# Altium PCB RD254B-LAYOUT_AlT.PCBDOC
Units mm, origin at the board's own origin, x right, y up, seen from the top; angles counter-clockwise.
Board outline 100 x 100 mm, 2 copper layers (TOP, BOTTOM), stack 0 mm thick; 50 components, 44 nets, 384 pads, 0 vias.
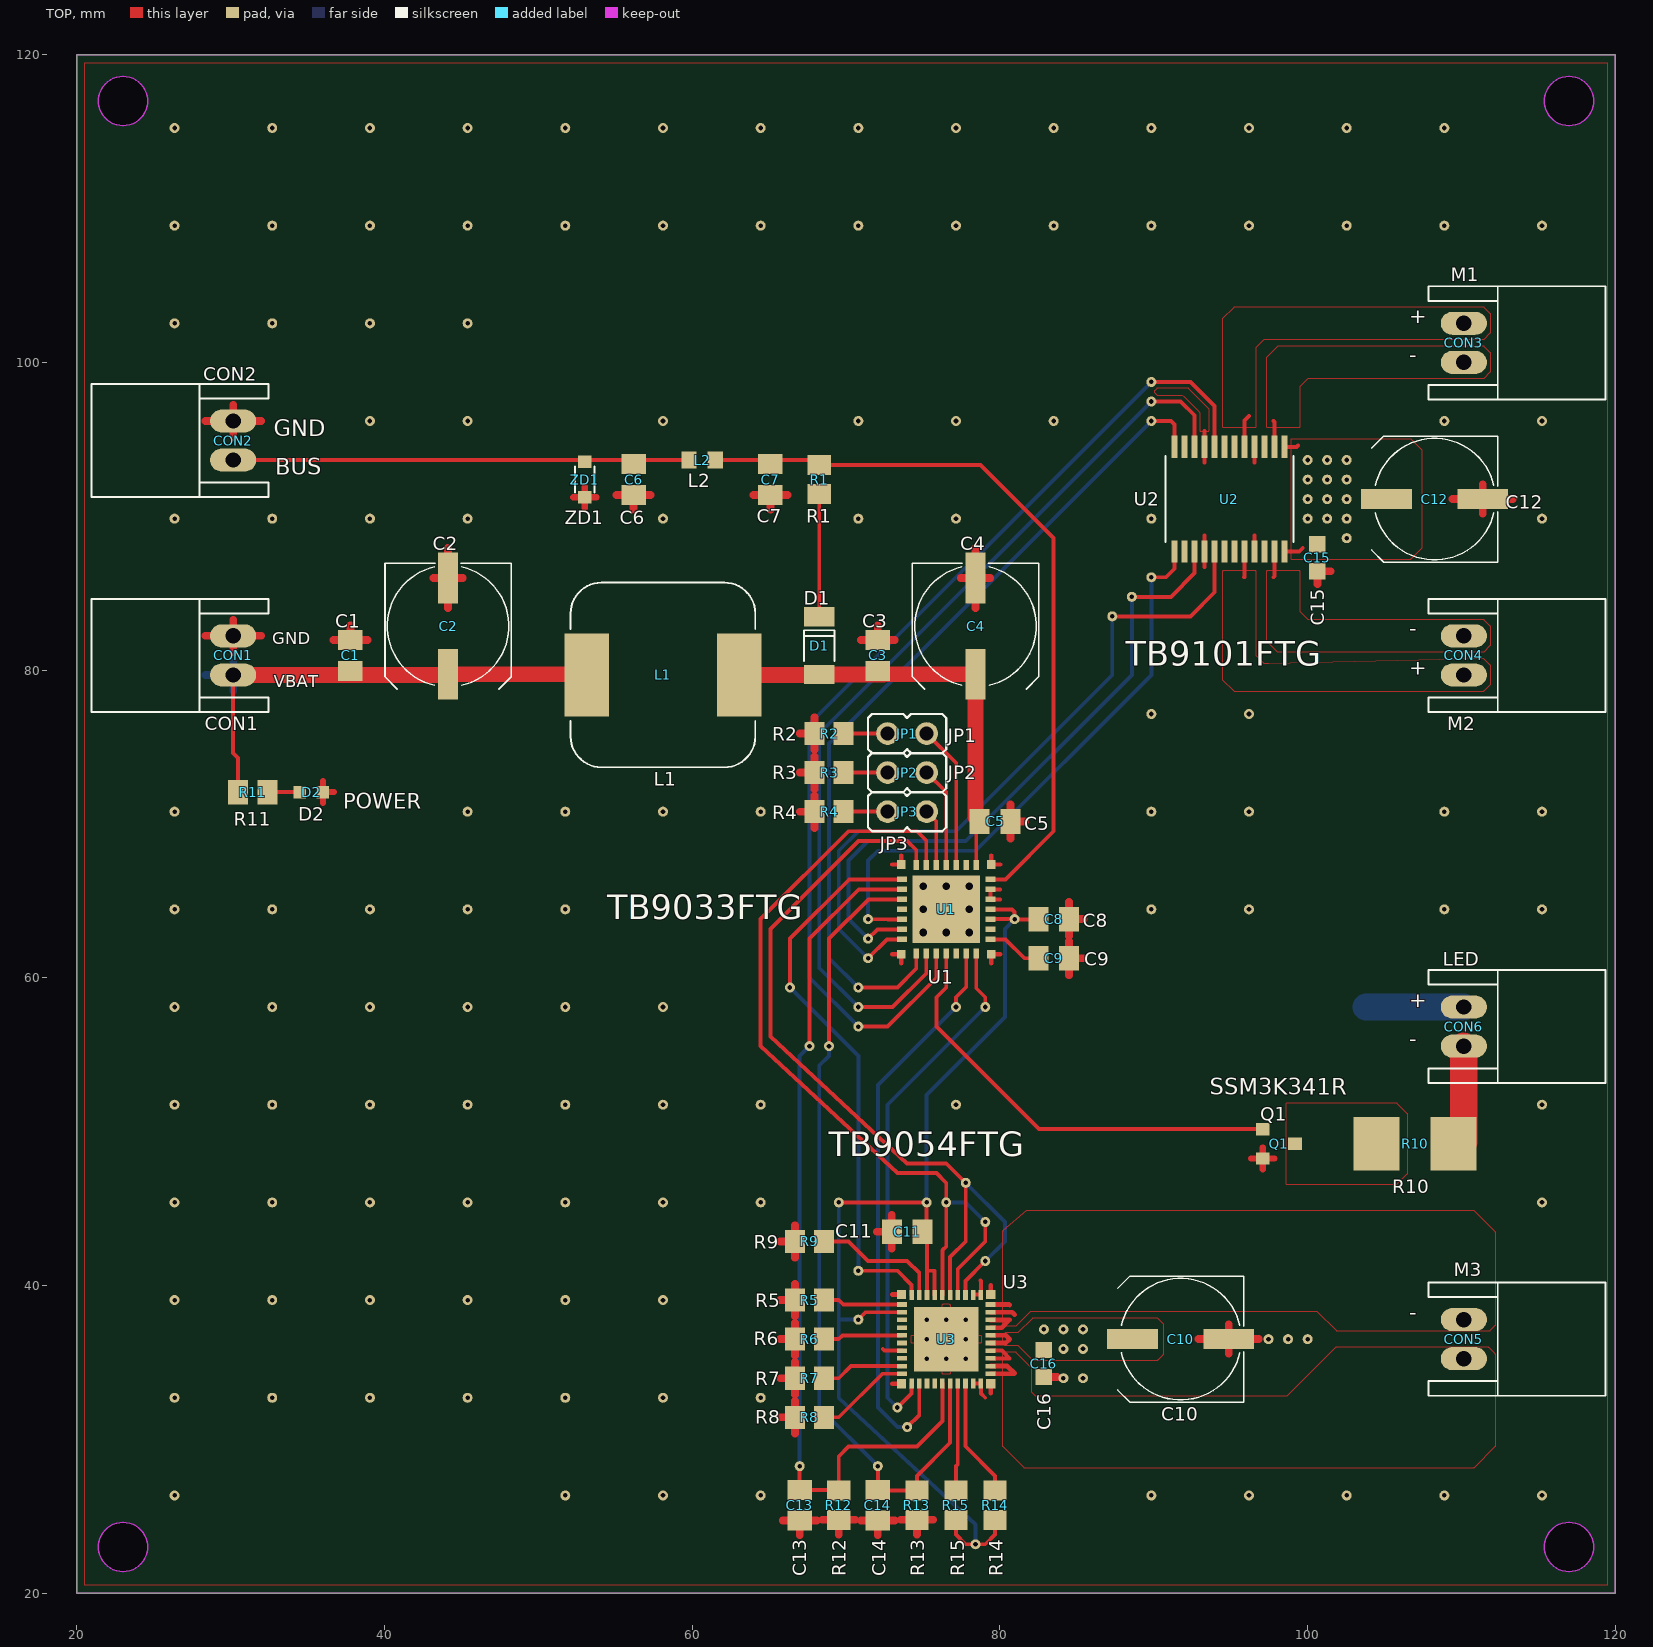
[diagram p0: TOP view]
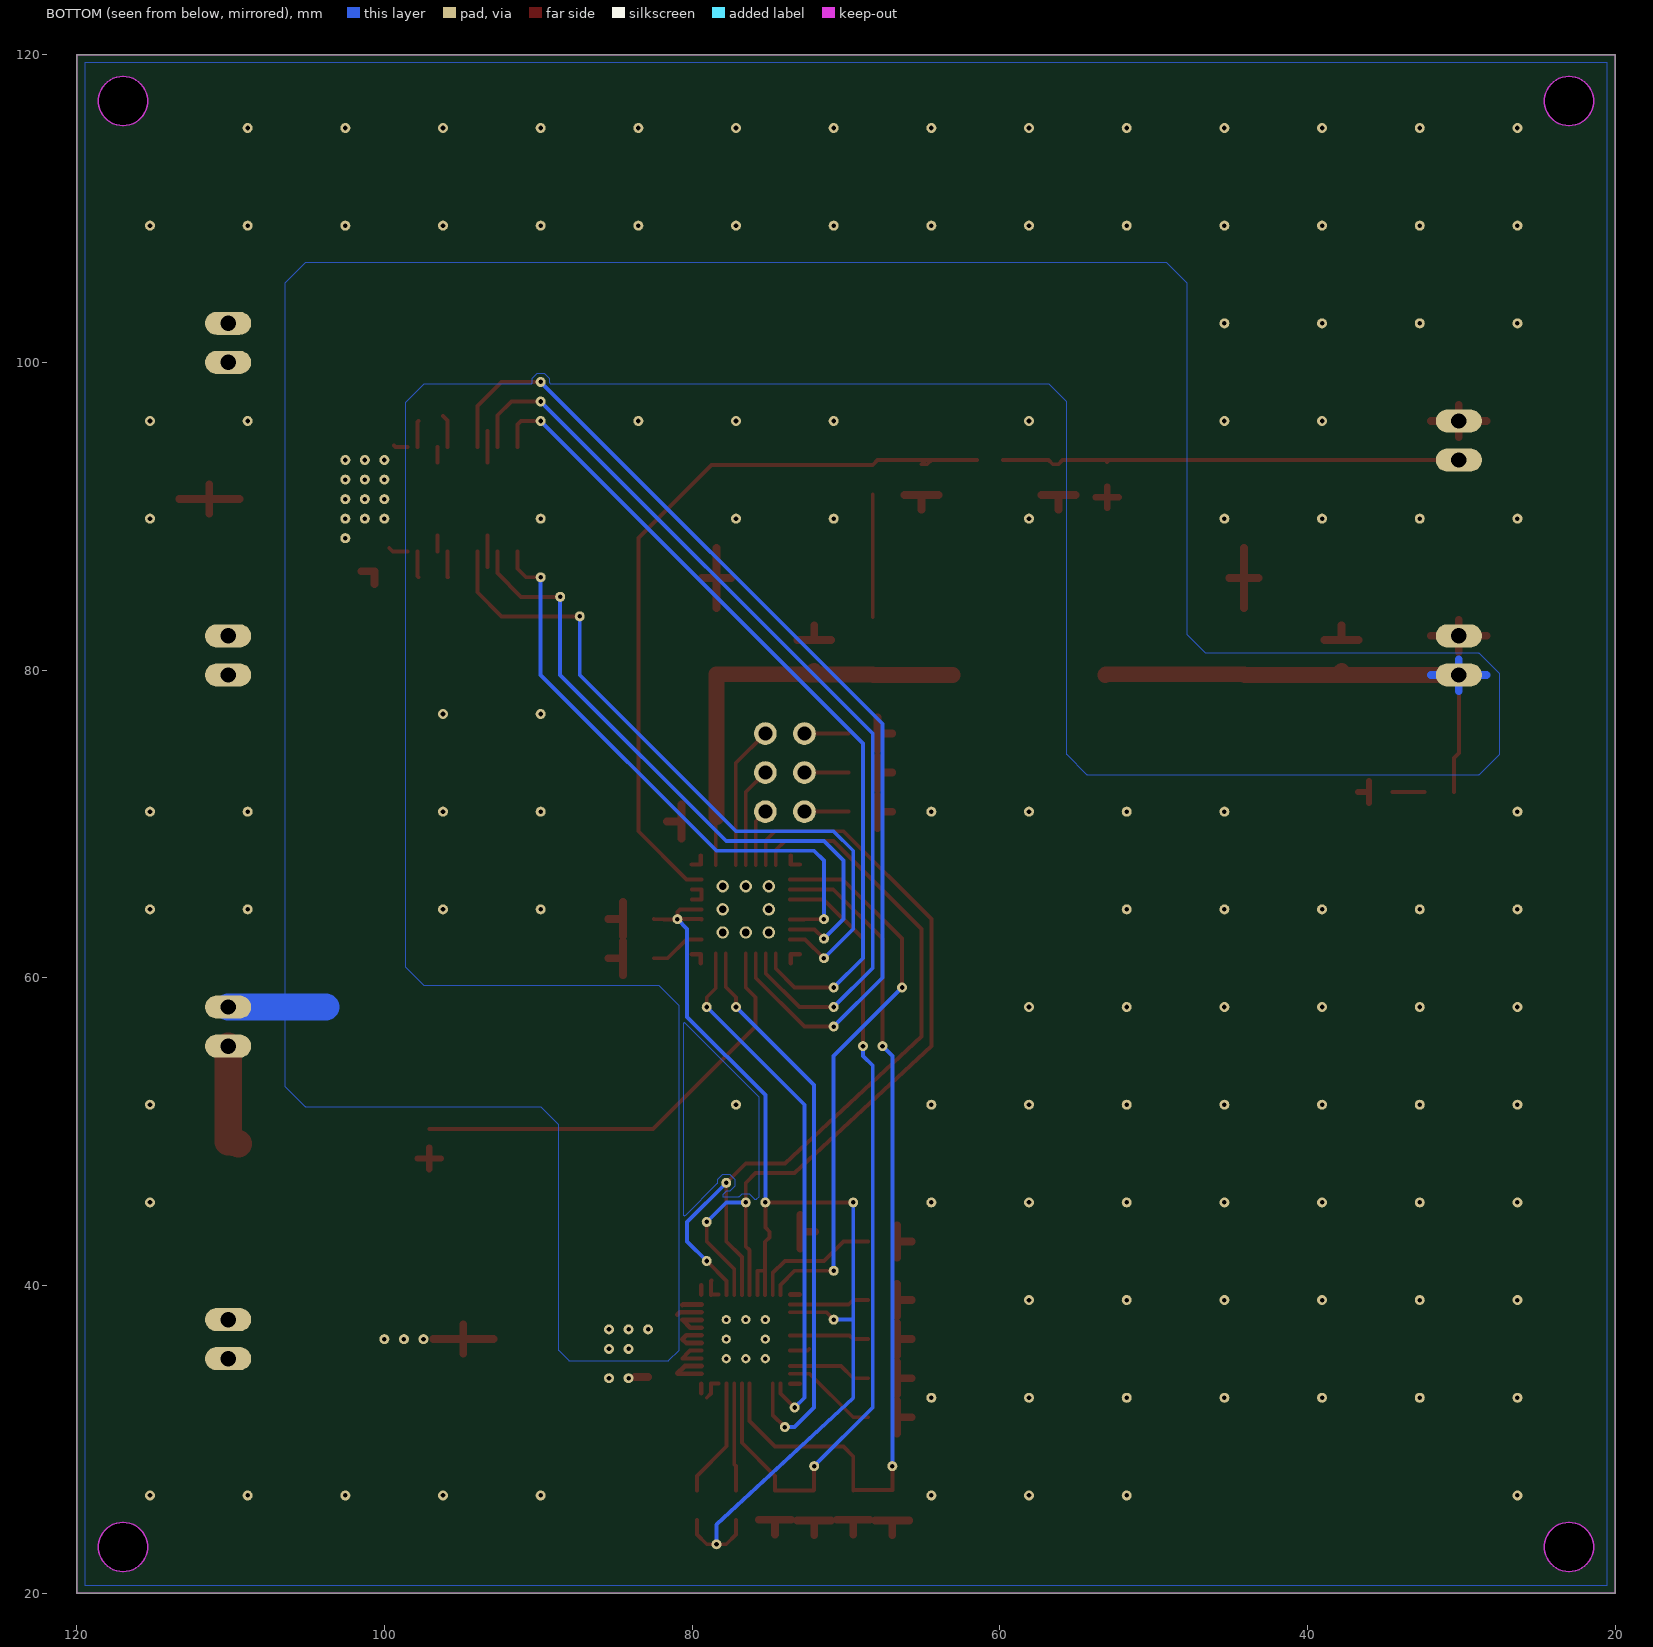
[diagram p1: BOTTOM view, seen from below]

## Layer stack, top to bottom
Top Solder: solder mask 0.0102, Solder Resist, Dk 3.5
TOP: signal copper (thickness not stored)
BOTTOM: signal copper (thickness not stored)
Bottom Solder: solder mask 0.0102, Solder Resist, Dk 3.5

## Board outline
20,20 20,120 120,120 120,20

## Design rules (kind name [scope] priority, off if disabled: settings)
AssemblyTestPointUsage [All] p0: scope1count=1 scope1_0_kind=Board scope1_0_value=Board scope2count=1 scope2_0_kind=Board scope2_0_value=Board commentlength=0
AssemblyTestpoint [All] p0: scope1count=1 scope1_0_kind=Board scope1_0_value=Board scope2count=1 scope2_0_kind=Board scope2_0_value=Board commentlength=0
Clearance [All] p0: scope1count=1 scope1_0_kind=Board scope1_0_value=Board scope2count=1 scope2_0_kind=Board scope2_0_value=Board commentlength=0 gap=0.254
Clearance [All] p1: gap=0.254 ignorepadtopadclearanceinfootprint=TRUE except(0.3: Arc-Hole Track-Hole SMDPad-Hole THPad-Hole Via-Hole Fill-Hole Poly-Hole Region-Hole Text-Hole)
ComponentClearance [All] p0: scope1count=1 scope1_0_kind=Board scope1_0_value=Board scope2count=1 scope2_0_kind=Board scope2_0_value=Board commentlength=0 gap=0.254 collisioncheckmode=3
DiffPairsRouting [All] p0: scope1count=1 scope1_0_kind=Board scope1_0_value=Board scope2count=1 scope2_0_kind=Board scope2_0_value=Board commentlength=0
FabricationTestPointUsage [All] p0: scope1count=1 scope1_0_kind=Board scope1_0_value=Board scope2count=1 scope2_0_kind=Board scope2_0_value=Board commentlength=0 valid=0 allowmultiple=FALSE
FabricationTestpoint [All] p0: scope1count=1 scope1_0_kind=Board scope1_0_value=Board scope2count=1 scope2_0_kind=Board scope2_0_value=Board commentlength=0 side=3 testpointundercomponent=TRUE minsize=1.016 maxsize=2.54 preferedsize=1.524 minholesize=0 maxholesize=1.016 preferedholesize=0.813 testpointgrid=0.025
FanoutControl Fanout_BGA [All] p0 off: scope1count=1 scope1_0_kind=Board scope1_0_value=Board scope2count=1 scope2_0_kind=Board scope2_0_value=Board commentlength=69 // Protel DXP Scope 1 Expression Was: IsBGA   Fanout_BGA (Default Rule)
FanoutControl Fanout_LCC [All] p0 off: scope1count=1 scope1_0_kind=Board scope1_0_value=Board scope2count=1 scope2_0_kind=Board scope2_0_value=Board commentlength=69 // Protel DXP Scope 1 Expression Was: IsLCC   Fanout_LCC (Default Rule)
FanoutControl Fanout_SOIC [All] p0 off: scope1count=1 scope1_0_kind=Board scope1_0_value=Board scope2count=1 scope2_0_kind=Board scope2_0_value=Board commentlength=71 // Protel DXP Scope 1 Expression Was: IsSOIC   Fanout_SOIC (Default Rule)
FanoutControl Fanout_Small [All] p0 off: scope1count=1 scope1_0_kind=Board scope1_0_value=Board scope2count=1 scope2_0_kind=Board scope2_0_value=Board commentlength=84 // Protel DXP Scope 1 Expression Was: (CompPinCount < 5)   Fanout_Small (Default Rule)
FanoutControl Fanout_Default [All] p0: scope1count=1 scope1_0_kind=Board scope1_0_value=Board scope2count=1 scope2_0_kind=Board scope2_0_value=Board commentlength=30 // Fanout_Default (Default Rule)
Height [All] p0: scope1count=1 scope1_0_kind=Board scope1_0_value=Board scope2count=1 scope2_0_kind=Board scope2_0_value=Board commentlength=0
HoleSize [All] p0: scope1count=1 scope1_0_kind=Board scope1_0_value=Board scope2count=1 scope2_0_kind=Board scope2_0_value=Board commentlength=0 absolutevalues=TRUE maxlimit=100 minlimit=0.001 maxpercent=80.000 minpercent=20.000
HoleSize [All] p1: absolutevalues=TRUE maxlimit=100 minlimit=0.001 maxpercent=80.000 minpercent=20.000
HoleToHoleClearance [All] p0: scope1count=1 scope1_0_kind=Board scope1_0_value=Board scope2count=1 scope2_0_kind=Board scope2_0_value=Board commentlength=0
HoleToHoleClearance [All] p1: gap=0.4 allowstackedmicrovias=FALSE
LayerPairs [All] p0: scope1count=1 scope1_0_kind=Board scope1_0_value=Board scope2count=1 scope2_0_kind=Board scope2_0_value=Board commentlength=0 enforce=TRUE
MinimumSolderMaskSliver [All] p0: scope1count=1 scope1_0_kind=Board scope1_0_value=Board scope2count=1 scope2_0_kind=Board scope2_0_value=Board commentlength=0
MinimumSolderMaskSliver [All] p1: minsoldermaskwidth=0.1
NetAntennae [All] p0: scope1count=1 scope1_0_kind=Board scope1_0_value=Board scope2count=1 scope2_0_kind=Board scope2_0_value=Board commentlength=0
NetAntennae [All] p1: netantennaetolerance=100
PasteMaskExpansion [All] p0: scope1count=1 scope1_0_kind=Board scope1_0_value=Board scope2count=1 scope2_0_kind=Board scope2_0_value=Board commentlength=0 expansion=0
PlaneClearance [All] p0: scope1count=1 scope1_0_kind=Board scope1_0_value=Board scope2count=1 scope2_0_kind=Board scope2_0_value=Board commentlength=0 clearance=0.001
PlaneClearance [All] p1: clearance=0.001
PlaneConnect [All] p0: scope1count=1 scope1_0_kind=Board scope1_0_value=Board scope2count=1 scope2_0_kind=Board scope2_0_value=Board commentlength=0 planeconnectstyle=Direct reliefexpansion=0.508 reliefentries=4 reliefconductorwidth=0.254 reliefairgap=0.254
PlaneConnect [All] p1: planeconnectstyle=Direct reliefexpansion=0.508 reliefentries=4 reliefconductorwidth=0.254 reliefairgap=0.254
PolygonConnect [All] p0: scope1count=1 scope1_0_kind=Board scope1_0_value=Board scope2count=1 scope2_0_kind=Board scope2_0_value=Board commentlength=0 connectstyle=Direct reliefconductorwidth=0.254 reliefentries=4 polygonreliefangle="90 Angle"
PolygonConnect [All] p1: connectstyle=Direct reliefconductorwidth=0.254 reliefentries=4 polygonreliefangle="90 Angle" airgapwidth=0.254
RoutingCorners [All] p0: scope1count=1 scope1_0_kind=Board scope1_0_value=Board scope2count=1 scope2_0_kind=Board scope2_0_value=Board commentlength=0 cornerstyle=45-Degree minsetback=2.54 maxsetback=2.54
RoutingLayers [All] p0: scope1count=1 scope1_0_kind=Board scope1_0_value=Board scope2count=1 scope2_0_kind=Board scope2_0_value=Board commentlength=0 top layer=Automatic bottom layer=Automatic
RoutingPriority [All] p0: scope1count=1 scope1_0_kind=Board scope1_0_value=Board scope2count=1 scope2_0_kind=Board scope2_0_value=Board commentlength=0
RoutingTopology [All] p0: scope1count=1 scope1_0_kind=Board scope1_0_value=Board scope2count=1 scope2_0_kind=Board scope2_0_value=Board commentlength=0 topology=Shortest
RoutingVias [All] p0: scope1count=1 scope1_0_kind=Board scope1_0_value=Board scope2count=1 scope2_0_kind=Board scope2_0_value=Board commentlength=0 holewidth=0.1 width=0.1 viastyle="Through Hole" minholewidth=0.001 minwidth=0.001 maxholewidth=100 maxwidth=100
RoutingVias [All] p1: holewidth=0.1 width=0.1 viastyle="Through Hole" minholewidth=0.001 minwidth=0.001 maxholewidth=100 maxwidth=100
ShortCircuit [All] p0: scope1count=1 scope1_0_kind=Board scope1_0_value=Board scope2count=1 scope2_0_kind=Board scope2_0_value=Board commentlength=0 allowed=FALSE
SilkToBoardRegionClearance [All] p0: scope1count=1 scope1_0_kind=Board scope1_0_value=Board scope2count=1 scope2_0_kind=Board scope2_0_value=Board commentlength=0
SilkToSilkClearance [All] p0: scope1count=1 scope1_0_kind=Board scope1_0_value=Board scope2count=1 scope2_0_kind=Board scope2_0_value=Board commentlength=0
SilkToSilkClearance [All] p1: silktosilkclearance=0.001
SilkToSolderMaskClearance [All] p0 off: scope1count=1 scope1_0_kind=Board scope1_0_value=Board scope2count=1 scope2_0_kind=Board scope2_0_value=Board commentlength=44 // Protel DXP Scope 1 Expression Was: IsPad
SilkToSolderMaskClearance [IsPad] p1: minsilkscreentomaskgap=0 clearancetoexposedcopper=TRUE
SolderMaskExpansion [All] p0: scope1count=1 scope1_0_kind=Board scope1_0_value=Board scope2count=1 scope2_0_kind=Board scope2_0_value=Board commentlength=0 expansion=0.001
SolderMaskExpansion [All] p1: expansion=0.001
UnRoutedNet [All] p0: scope1count=1 scope1_0_kind=Board scope1_0_value=Board scope2count=1 scope2_0_kind=Board scope2_0_value=Board commentlength=0
UnpouredPolygon [All] p0: scope1count=1 scope1_0_kind=Board scope1_0_value=Board scope2count=1 scope2_0_kind=Board scope2_0_value=Board commentlength=0
Width [All] p0: scope1count=1 scope1_0_kind=Board scope1_0_value=Board scope2count=1 scope2_0_kind=Board scope2_0_value=Board commentlength=0 maxlimit=1000 minlimit=2539.975 preferedwidth=0
Width [All] p1: maxlimit=1000 minlimit=2539.975 preferedwidth=0 toplayer_minwidth=0 bottomlayer_minwidth=0 minimp=50.000000 maximp=50.000000 favimp=50.000000
22 further rules are at their usual default settings.

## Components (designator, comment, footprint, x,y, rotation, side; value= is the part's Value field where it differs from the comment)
C1 "C0805K" C0805K 37.78,80.96 r90 top
C2 "UD-8X10_NICHICON_01" UD-8X10_NICHICON_01 44.13,82.865 r270 top
C3 "C0805K" C0805K 72.07,80.96 r90 top
C4 "UD-8X10_NICHICON_01" UD-8X10_NICHICON_01 78.42,82.865 r270 top
C5 "C0805K" C0805K 79.69,70.165 r0 top
C6 "C0805K" C0805K 56.195,92.39 r270 top
C7 "C0805K" C0805K 65.085,92.39 r270 top
C8 "C0805K" C0805K 83.5,63.815 r180 top
C9 "C0805K" C0805K 83.5,61.275 r180 top
C10 "UD-8X10_NICHICON_01" UD-8X10_NICHICON_01 91.755,36.51 r180 top
C11 "C0805K" C0805K 73.975,43.495 r0 top
C12 "UD-8X10_NICHICON_01" UD-8X10_NICHICON_01 108.265,91.12 r180 top
C13 "C0805K" C0805K 66.99,25.715 r270 top
C14 "C0805K" C0805K 72.07,25.715 r270 top
C15 "C0603K" C0603K 100.645,87.31 r270 top
C16 "C0603K" C0603K 82.865,34.923 r270 top
cam1 "A4L-LOC" A4L-LOC -50,-27 r0 top
CON1 "S2B-XH-A" S2B-XH-A 30.16,80.96 r90 top
CON2 "S2B-XH-A" S2B-XH-A 30.16,94.93 r90 top
CON3 "S2B-XH-A" S2B-XH-A 110.17,101.28 r270 top
CON4 "S2B-XH-A" S2B-XH-A 110.17,80.96 r270 top
CON5 "S2B-XH-A" S2B-XH-A 110.17,36.51 r270 top
CON6 "S2B-XH-A" S2B-XH-A 110.17,56.83 r270 top
D1 "LL4148" LL4148 68.26,81.595 r90 top
D2 "CHIP-LED0603" CHIP-LED0603 35.24,72.07 r270 top
JP1 "JP1" JP1 73.975,75.88 r270 top
JP2 "JP1" JP1 73.975,73.34 r270 top
JP3 "JP1" JP1 73.975,70.8 r270 top
L1 "7447709222" 7447709222 58.1,79.69 r270 top
L2 "R0603" R0603 60.64,93.66 r0 top
Q1 "SOT-23F" SOT-23F 98.74,49.21 r270 top
R1 "R0805" R0805 68.26,92.39 r270 top
R2 "R0805" R0805 68.895,75.88 r180 top
R3 "R0805" R0805 68.895,73.34 r180 top
R4 "R0805" R0805 68.895,70.8 r180 top
R5 "R0805" R0805 67.625,39.05 r180 top
R6 "R0805" R0805 67.625,36.51 r180 top
R7 "R0805" R0805 67.625,33.97 r180 top
R8 "R0805" R0805 67.625,31.43 r180 top
R9 "R0805" R0805 67.625,42.86 r180 top
R10 "R2512-2010" R2512-2010 106.995,49.21 r0 top
R11 "M0805" M0805 31.43,72.07 r180 top
R12 "R0805" R0805 69.53,25.715 r270 top
R13 "R0805" R0805 74.61,25.715 r270 top
R14 "R0805" R0805 79.69,25.715 r90 top
R15 "R0805" R0805 77.15,25.715 r90 top
U1 "P-VQFN28-0606-0_65-003_01" P-VQFN28-0606-0_65-003_01 76.515,64.45 r180 top
U2 "SSOP24-P-300-0_65A" SSOP24-P-300-0_65A 94.93,91.12 r90 top
U3 "P-VQFN40-0606-0_50-001_01" P-VQFN40-0606-0_50-001_01 76.515,36.51 r270 top
ZD1 "USC" USC 53.02,92.39 r270 top

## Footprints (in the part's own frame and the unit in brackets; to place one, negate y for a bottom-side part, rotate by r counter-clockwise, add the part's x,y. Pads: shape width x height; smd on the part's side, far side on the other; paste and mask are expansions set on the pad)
7447709222 [mm] "KC00080BKP"
  rect 5.4x2.9 smd paste-5.603 mask+0: 1(0,-4.95) 2(0,4.95)
  silkscreen extent -6,-6 6,6
A4L-LOC [mm] "KC00080BKP"
C0603K [mm] "KC00080BKP"
  rect 1.05x1.08 smd paste-1.283 mask+0: 1(-0.875,0) 2(0.875,0)
C0805K [mm] "KC00080BKP"
  rect 1.3x1.6 smd paste-1.803 mask+0: 1(-1,0) 2(1,0)
CHIP-LED0603 [mm] "KC00080BKP"
  rect 0.8x0.8 smd paste-1.003 mask+0: A(0,-0.75) C(0,0.75)
JP1 [mm] "KC00080BKP"
  round 1.48 / inner round 0 / far side round 1.48 hole 0.914 paste-1.68 mask+0: 1(0,-1.27) 2(0,1.27)
  silkscreen extent -1.27,-2.54 1.27,2.54
LL4148 [mm] "KC00080BKP"
  rect 1.25x2 smd paste-2.203 mask+0: A(-1.875,0) K(1.875,0)
  silkscreen extent -1,-1 1,1
M0805 [mm] "KC00080BKP"
  rect 1.3x1.6 smd paste-1.803 mask+0: 1(-0.95,0) 2(0.95,0)
P-VQFN28-0606-0_65-003_01 [mm] "KC00080BKP"
  rect 0.35x0.65 smd paste-0.853 mask+0: 1(-1.95,-2.875) 2(-1.3,-2.875) 3(-0.65,-2.875) 4(0,-2.875) 5(0.65,-2.875) 6(1.3,-2.875) 7(1.95,-2.875) 15(1.95,2.875) 16(1.3,2.875) 17(0.65,2.875) 18(0,2.875) 19(-0.65,2.875) 20(-1.3,2.875) 21(-1.95,2.875)
  rect 0.56x0.56 smd paste-0.763 mask+0: 1T(-2.92,-2.92) 2T(2.92,-2.92) 3T(2.92,2.92) 4T(-2.92,2.92)
  rect 0.65x0.35 smd paste-0.853 mask+0: 8(2.875,-1.95) 9(2.875,-1.3) 10(2.875,-0.65) 11(2.875,0) 12(2.875,0.65) 13(2.875,1.3) 14(2.875,1.95) 22(-2.875,1.95) 23(-2.875,1.3) 24(-2.875,0.65) 25(-2.875,0) 26(-2.875,-0.65) 27(-2.875,-1.3) 28(-2.875,-1.95)
  rect 4.4x4.4 smd paste-4.603 mask+0: E_PAD(0,0)
  round 0.803 / inner round 0 / far side round 0.803 hole 0.5 paste-1.05 mask+0: ""(-1.5,1.5) ""(-1.5,0) ""(-1.5,-1.5) ""(0,1.5) ""(0,-1.5) ""(1.5,1.5) ""(1.5,0) ""(1.5,-1.5)
P-VQFN40-0606-0_50-001_01 [mm] "KC00080BKP"
  rect 0.3x0.65 smd paste-0.853 mask+0: 1(-2.25,-2.875) 2(-1.75,-2.875) 3(-1.25,-2.875) 4(-0.75,-2.875) 5(-0.25,-2.875) 6(0.25,-2.875) 7(0.75,-2.875) 8(1.25,-2.875) 9(1.75,-2.875) 10(2.25,-2.875) 21(2.25,2.875) 22(1.75,2.875) 23(1.25,2.875) 24(0.75,2.875) 25(0.25,2.875) 26(-0.25,2.875) 27(-0.75,2.875) 28(-1.25,2.875) 29(-1.75,2.875) 30(-2.25,2.875)
  rect 0.6x0.6 smd paste-0.803 mask+0: 1T(2.9,-2.9) 2T(2.9,2.9) 3T(-2.9,2.9) 4T(-2.9,-2.9)
  rect 0.65x0.3 smd paste-0.853 mask+0: 11(2.875,-2.25) 12(2.875,-1.75) 13(2.875,-1.25) 14(2.875,-0.75) 15(2.875,-0.25) 16(2.875,0.25) 17(2.875,0.75) 18(2.875,1.25) 19(2.875,1.75) 20(2.875,2.25) 31(-2.875,2.25) 32(-2.875,1.75) 33(-2.875,1.25) 34(-2.875,0.75) 35(-2.875,0.25) 36(-2.875,-0.25) 37(-2.875,-0.75) 38(-2.875,-1.25) 39(-2.875,-1.75) 40(-2.875,-2.25)
  rect 4.2x4.2 smd paste-4.403 mask+0: E_PAD(0,0)
  round 0.6 / inner round 0 / far side round 0.6 hole 0.3 paste-0.803 mask+0: ""(-1.27,1.27) ""(-1.27,0) ""(-1.27,-1.27) ""(0,1.27) ""(0,-1.27) ""(1.27,1.27) ""(1.27,0) ""(1.27,-1.27)
R0603 [mm] "KC00080BKP"
  rect 1x1.1 smd paste-1.303 mask+0: 1(-0.85,0) 2(0.85,0)
R0805 [mm] "KC00080BKP"
  rect 1.3x1.5 smd paste-1.703 mask+0: 1(-0.95,0) 2(0.95,0)
R2512-2010 [mm] "KC00080BKP"
  rect 3x3.5 smd paste-3.703 mask+0: P_1(-2.5,0) P_2(2.5,0)
S2B-XH-A [mm] "KC00080BKP"
  oval 1.5x3 / inner round 0 / far side oval 1.5x3 hole 1 paste-3.203 mask+0: 1(1.27,0) 2(-1.27,0)
  silkscreen extent -3.68,-2.3 3.68,9.2
SOT-23F [mm] "KC00080BKP"
  rect 0.8x0.9 smd paste-1.103 mask+0: 1(-0.95,-1.65) 2(0.95,-1.65) 3(0,0.45)
SSOP24-P-300-0_65A [mm] "KC00080BKP"
  rect 1.45x0.4 smd paste-1.653 mask+0: 1(-3.4,3.575) 2(-3.4,2.925) 3(-3.4,2.275) 4(-3.4,1.625) 5(-3.4,0.975) 6(-3.4,0.325) 7(-3.4,-0.325) 8(-3.4,-0.975) 9(-3.4,-1.625) 10(-3.4,-2.275) 11(-3.4,-2.925) 12(-3.4,-3.575) 13(3.4,-3.575) 14(3.4,-2.925) 15(3.4,-2.275) 16(3.4,-1.625) 17(3.4,-0.975) 18(3.4,-0.325) 19(3.4,0.325) 20(3.4,0.975) 21(3.4,1.625) 22(3.4,2.275) 23(3.4,2.925) 24(3.4,3.575)
  silkscreen extent -2.8,-4.15 2.8,4.15
UD-8X10_NICHICON_01 [mm] "KC00080BKP"
  rect 3.3x1.3 smd paste-3.503 mask+0: 1(-3.125,0) 2(3.125,0)
  silkscreen extent -4.1,-4.1 4.1,4.1
USC [mm] "KC00080BKP"
  rect 0.8x0.9 smd paste-1.103 mask+0: 1(-1.15,0) 2(1.15,0)
  silkscreen extent -0.85,-0.63 0.85,0.63

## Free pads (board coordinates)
  round 0 hole 3.2 unplated paste-3.4 mask+0: ""(23,23) ""(23,117) ""(117,23) ""(117,117)
  round 0.65 / inner round 0 / far side round 0.65 hole 0.3 paste-0.65 mask+0: ""(26.35,26.35) ""(26.35,32.7) ""(26.35,39.05) ""(26.35,45.4) ""(26.35,51.75) ""(26.35,58.1) ""(26.35,64.45) ""(26.35,70.8) ""(26.35,89.85) ""(26.35,102.55) ""(26.35,108.9) ""(26.35,115.25) ""(32.7,32.7) ""(32.7,39.05) ""(32.7,45.4) ""(32.7,51.75) ""(32.7,58.1) ""(32.7,64.45) ""(32.7,89.85) ""(32.7,102.55) ""(32.7,108.9) ""(32.7,115.25) ""(39.05,32.7) ""(39.05,39.05) ""(39.05,45.4) ""(39.05,51.75) ""(39.05,58.1) ""(39.05,64.45) ""(39.05,89.85) ""(39.05,96.2) ""(39.05,102.55) ""(39.05,108.9) ""(39.05,115.25) ""(45.4,32.7) ""(45.4,39.05) ""(45.4,45.4) ""(45.4,51.75) ""(45.4,58.1) ""(45.4,64.45) ""(45.4,70.8) ""(45.4,89.85) ""(45.4,96.2) ""(45.4,102.55) ""(45.4,108.9) ""(45.4,115.25) ""(51.75,26.35) ""(51.75,32.7) ""(51.75,39.05) ""(51.75,45.4) ""(51.75,51.75) ""(51.75,58.1) ""(51.75,64.45) ""(51.75,70.8) ""(51.75,108.9) ""(51.75,115.25) ""(58.1,26.35) ""(58.1,32.7) ""(58.1,39.05) ""(58.1,45.4) ""(58.1,51.75) ""(58.1,58.1) ""(58.1,70.8) ""(58.1,89.85) ""(58.1,96.2) ""(58.1,108.9) ""(58.1,115.25) ""(64.45,26.35) ""(64.45,32.7) ""(64.45,45.4) ""(64.45,51.75) ""(64.45,70.8) ""(64.45,108.9) ""(64.45,115.25) ""(66.355,59.37) ""(66.99,28.255) ""(67.625,55.56) ""(68.895,55.56) ""(69.53,45.4) ""(70.8,37.78) ""(70.8,40.955) ""(70.8,56.83) ""(70.8,58.1) ""(70.8,59.37) ""(70.8,89.85) ""(70.8,96.2) ""(70.8,108.9) ""(70.8,115.25) ""(71.435,61.275) ""(71.435,62.545) ""(71.435,63.815) ""(72.07,28.255) ""(73.34,32.065) ""(73.975,30.795) ""(75.245,45.4) ""(76.515,45.4) ""(77.15,51.75) ""(77.15,58.1) ""(77.15,89.85) ""(77.15,96.2) ""(77.15,108.9) ""(77.15,115.25) ""(77.785,46.67) ""(78.42,23.175) ""(79.055,41.59) ""(79.055,44.13) ""(79.055,58.1) ""(80.96,63.815) ""(82.865,37.145) ""(83.5,96.2) ""(83.5,108.9) ""(83.5,115.25) ""(84.135,33.97) ""(84.135,35.875) ""(84.135,37.145) ""(85.405,33.97) ""(85.405,35.875) ""(85.405,37.145) ""(87.31,83.5) ""(88.58,84.77) ""(89.85,26.35) ""(89.85,64.45) ""(89.85,70.8) ""(89.85,77.15) ""(89.85,86.04) ""(89.85,89.85) ""(89.85,96.2) ""(89.85,97.47) ""(89.85,98.74) ""(89.85,108.9) ""(89.85,115.25) ""(96.2,26.35) ""(96.2,64.45) ""(96.2,70.8) ""(96.2,77.15) ""(96.2,108.9) ""(96.2,115.25) ""(97.47,36.51) ""(98.74,36.51) ""(100.01,36.51) ""(100.01,89.85) ""(100.01,91.12) ""(100.01,92.39) ""(100.01,93.66) ""(101.28,89.85) ""(101.28,91.12) ""(101.28,92.39) ""(101.28,93.66) ""(102.55,26.35) ""(102.55,88.58) ""(102.55,89.85) ""(102.55,91.12) ""(102.55,92.39) ""(102.55,93.66) ""(102.55,108.9) ""(102.55,115.25) ""(108.9,26.35) ""(108.9,64.45) ""(108.9,70.8) ""(108.9,96.2) ""(108.9,108.9) ""(108.9,115.25) ""(115.25,26.35) ""(115.25,45.4) ""(115.25,51.75) ""(115.25,64.45) ""(115.25,70.8) ""(115.25,89.85) ""(115.25,96.2) ""(115.25,108.9)

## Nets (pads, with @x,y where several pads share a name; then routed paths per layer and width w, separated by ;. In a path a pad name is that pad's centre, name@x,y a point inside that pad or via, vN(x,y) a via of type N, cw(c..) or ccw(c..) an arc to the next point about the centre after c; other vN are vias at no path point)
+12V: C1.1 C2.2 C10.2 C12.2 C15.1 C16.1 CON1.2 CON6.2 L1.1 pad.@82.865,37.145 pad.@84.135,35.875 pad.@84.135,37.145 pad.@85.405,35.875 pad.@85.405,37.145 pad.@100.01,89.85 pad.@100.01,91.12 pad.@100.01,92.39 pad.@100.01,93.66 pad.@101.28,89.85 pad.@101.28,91.12 pad.@101.28,92.39 pad.@101.28,93.66 pad.@102.55,88.58 pad.@102.55,89.85 pad.@102.55,91.12 pad.@102.55,92.39 pad.@102.55,93.66 R11.2 U2.12 U2.13 U3.25 U3.26 | length 48.4
  TOP w0.254: CON1.2 30.16,74.61 30.48,74.29 R11.2 ; U2.12 99.467,87.72 99.693,87.945 ; U2.13 99.282,94.52 99.375,94.613
  TOP w0.305: U3.25 80.393,36.26 80.643,36.51 80.393,36.76 U3.26
  TOP w1.016: CON1.2 C1.1@37.78,79.69 ; L1.1 53.1,79.74 C2.2 44.08,79.69 C1.1@38.145,79.69 ; C1.1@37.78,79.69 C1.1@38.145,79.69 ; C1.1@37.78,79.69 C1.1 C1.1@38.145,79.69
  BOTTOM w0.5: 28.355,79.69 CON1.2 ; 30.16,78.635 CON1.2 ; 30.16,80.694 CON1.2 ; 31.965,79.69 CON1.2
  BOTTOM w1.778: 103.82,58.1 CON6.2
BUS: C7.1 L2.2 R1.1 U1.28 | length 49.7
  TOP w0.254: L2.2 C7.1@64.45,93.66 ; U1.28 80.37,66.4 83.5,69.53 83.5,88.58 78.74,93.34 R1.1 67.94,93.66 C7.1@64.815,93.66 ; C7.1@64.45,93.66 64.72,93.39 C7.1 C7.1@64.815,93.66 ; C7.1@64.45,93.66 C7.1@64.815,93.66
GND: C1.2 C2.1 C3.2 C4.1 C5.2 C6.2 C7.2 C8.1 C9.1 C10.1 C11.1 C12.1 C13.2 C14.2 C15.2 C16.2 CON1.1 CON2.1 D2.C pad.@26.35,26.35 pad.@26.35,32.7 pad.@26.35,39.05 pad.@26.35,45.4 pad.@26.35,51.75 pad.@26.35,58.1 pad.@26.35,64.45 pad.@26.35,70.8 pad.@26.35,89.85 pad.@26.35,102.55 pad.@26.35,108.9 pad.@26.35,115.25 pad.@32.7,32.7 pad.@32.7,39.05 pad.@32.7,45.4 pad.@32.7,51.75 pad.@32.7,58.1 pad.@32.7,64.45 pad.@32.7,89.85 pad.@32.7,102.55 pad.@32.7,108.9 pad.@32.7,115.25 pad.@39.05,32.7 pad.@39.05,39.05 pad.@39.05,45.4 pad.@39.05,51.75 pad.@39.05,58.1 pad.@39.05,64.45 pad.@39.05,89.85 pad.@39.05,96.2 pad.@39.05,102.55 pad.@39.05,108.9 pad.@39.05,115.25 pad.@45.4,32.7 pad.@45.4,39.05 pad.@45.4,45.4 pad.@45.4,51.75 pad.@45.4,58.1 pad.@45.4,64.45 pad.@45.4,70.8 pad.@45.4,89.85 pad.@45.4,96.2 pad.@45.4,102.55 pad.@45.4,108.9 pad.@45.4,115.25 pad.@51.75,26.35 pad.@51.75,32.7 pad.@51.75,39.05 pad.@51.75,45.4 pad.@51.75,51.75 pad.@51.75,58.1 pad.@51.75,64.45 pad.@51.75,70.8 pad.@51.75,108.9 pad.@51.75,115.25 pad.@58.1,26.35 pad.@58.1,32.7 pad.@58.1,39.05 pad.@58.1,45.4 pad.@58.1,51.75 pad.@58.1,58.1 pad.@58.1,70.8 pad.@58.1,89.85 pad.@58.1,96.2 pad.@58.1,108.9 pad.@58.1,115.25 pad.@64.45,26.35 pad.@64.45,32.7 pad.@64.45,45.4 pad.@64.45,51.75 pad.@64.45,70.8 pad.@64.45,108.9 pad.@64.45,115.25 pad.@70.8,89.85 pad.@70.8,96.2 pad.@70.8,108.9 pad.@70.8,115.25 pad.@77.15,51.75 pad.@77.15,89.85 pad.@77.15,96.2 pad.@77.15,108.9 pad.@77.15,115.25 pad.@83.5,96.2 pad.@83.5,108.9 pad.@83.5,115.25 pad.@84.135,33.97 pad.@85.405,33.97 pad.@89.85,26.35 pad.@89.85,64.45 pad.@89.85,70.8 pad.@89.85,77.15 pad.@89.85,89.85 pad.@89.85,108.9 pad.@89.85,115.25 pad.@96.2,26.35 pad.@96.2,64.45 pad.@96.2,70.8 pad.@96.2,77.15 pad.@96.2,108.9 pad.@96.2,115.25 pad.@97.47,36.51 pad.@98.74,36.51 pad.@100.01,36.51 pad.@102.55,26.35 pad.@102.55,108.9 pad.@102.55,115.25 pad.@108.9,26.35 pad.@108.9,64.45 pad.@108.9,70.8 pad.@108.9,96.2 pad.@108.9,108.9 pad.@108.9,115.25 pad.@115.25,26.35 pad.@115.25,45.4 pad.@115.25,51.75 pad.@115.25,64.45 pad.@115.25,70.8 pad.@115.25,89.85 pad.@115.25,96.2 pad.@115.25,108.9 Q1.2 R2.2 R3.2 R4.2 R5.2 R6.2 R7.2 R8.2 R9.2 R12.2 R13.2 U1. U1.1T U1.2T U1.3T U1.4T U1.26 U1.27 U2.4 U2.9 U2.16 U2.21 U3. U3.1T U3.2T U3.3T U3.7 U3.19 U3.20 U3.31 U3.32 U3.E_PAD ZD1.2 | length 126.9
  TOP w0.254: 72.388,35.875 72.502,35.76 U3.7 ; U3.19@78.288,33.635 U3.20 78.765,32.99 79.055,32.7 ; U3.32@78.288,39.4 U3.31@78.742,39.4 ; 78.738,40.32 78.765,40.293 U3.31 ; 80.02,65.1 U1.26 U1.27 80.02,65.75 ; 93.305,86.69 U2.4 93.305,88.75 ; 93.305,93.49 U2.21 93.305,95.55 ; U2.9 96.555,88.75 ; 96.555,93.49 U2.16
  TOP w0.28: 73.01,61.53 U1.3T 73.595,60.945 ; 73.01,67.37 U1.2T 73.595,67.955 ; 79.435,60.945 U1.4T 80.02,61.53 ; 79.435,67.955 U1.1T 80.02,67.37
  TOP w0.3: 73.01,33.61 U3.1T ; 73.01,39.41 73.615,39.41 ; 79.415,33.005 U3.2T ; U3.3T 79.415,40.015
  TOP w0.4: 35.99,71.365 D2.C ; 35.99,72.775 D2.C ; 36.695,72.07 D2.C ; 52.265,91.24 ZD1.2 ; 53.02,90.535 ZD1.2 ; 53.02,91.945 ZD1.2 ; 53.775,91.24 ZD1.2 ; 96.335,48.26 Q1.2 ; 97.09,47.555 Q1.2 ; 97.09,48.965 Q1.2 ; 97.845,48.26 Q1.2
  TOP w0.5: 28.355,82.23 CON1.1 ; 28.355,96.2 CON2.1 ; 30.16,81.175 CON1.1 ; 30.16,83.285 CON1.1 ; 30.16,95.145 CON2.1 ; 30.16,97.255 CON2.1 ; 31.965,82.23 CON1.1 ; 31.965,96.2 CON2.1
  TOP w0.508: 36.675,81.96 C1.2 ; 37.78,82.915 C1.2 ; 38.885,81.96 C1.2 ; 43.175,85.99 C2.1 ; 44.13,84.035 C2.1 ; 44.13,87.945 C2.1 ; 45.085,85.99 C2.1 ; 55.09,91.39 C6.2 ; 56.195,90.435 C6.2 ; 57.3,91.39 C6.2 ; 63.98,91.39 C7.2 ; 65.085,90.435 C7.2 ; 65.72,31.43 R8.2 ; 65.72,33.97 R7.2 ; 65.72,36.51 R6.2 ; 65.72,39.05 R5.2 ; 65.72,42.86 R9.2 ; 65.885,24.715 C13.2 ; 66.19,91.39 C7.2 ; 66.675,30.375 R8.2 ; 66.675,32.485 R8.2 ; 66.675,32.915 R7.2 ; 66.675,35.025 R7.2 ; 66.675,35.455 R6.2 ; 66.675,37.565 R6.2 ; 66.675,37.995 R5.2 ; 66.675,40.105 R5.2 ; 66.675,41.805 R9.2 ; 66.675,43.915 R9.2 ; 66.99,23.76 C13.2 ; 66.99,70.8 R4.2 ; 66.99,73.34 R3.2 ; 66.99,75.88 R2.2 ; 67.945,69.745 R4.2 ; 67.945,71.855 R4.2 ; 67.945,72.285 R3.2 ; 67.945,74.395 R3.2 ; 67.945,74.825 R2.2 ; 67.945,76.935 R2.2 ; 68.095,24.715 C13.2 ; 68.475,24.765 R12.2 ; 69.53,23.81 R12.2 ; 70.585,24.765 R12.2 ; 70.965,24.715 C14.2 ; 70.965,81.96 C3.2 ; 72.02,43.495 C11.1 ; 72.07,23.76 C14.2 ; 72.07,82.915 C3.2 ; 72.975,42.39 C11.1 ; 72.975,44.6 C11.1 ; 73.175,24.715 C14.2 ; 73.175,81.96 C3.2 ; 73.555,24.765 R13.2 ; 74.61,23.81 R13.2 ; 75.665,24.765 R13.2 ; 77.465,85.99 C4.1 ; 78.42,84.035 C4.1 ; 78.42,87.945 C4.1 ; 79.375,85.99 C4.1 ; 80.69,69.06 C5.2 ; 80.69,71.27 C5.2 ; 81.645,70.165 C5.2 ; C16.2 83.71,34.048 ; 84.5,60.17 C9.1 ; 84.5,62.38 C9.1 ; 84.5,62.71 C8.1 ; 84.5,64.92 C8.1 ; 85.455,61.275 C9.1 ; 85.455,63.815 C8.1 ; 92.925,36.51 C10.1 ; 94.88,35.555 C10.1 ; 94.88,37.465 C10.1 ; 96.835,36.51 C10.1 ; 100.645,85.605 C15.2 101.49,86.435 ; 109.435,91.12 C12.1 ; 111.39,90.165 C12.1 ; 111.39,92.075 C12.1 ; 113.345,91.12 C12.1
N_1: D1.K R1.2 | length 8
  TOP w0.254: D1.K R1.2
N_2: JP3.2 U1.5 | length 3.7
  TOP w0.254: JP3.2 75.865,70.18 U1.5
N_3: JP2.2 U1.4 | length 6.5
  TOP w0.254: JP2.2 76.515,72.07 U1.4
N_4: JP1.2 U1.3 | length 9.4
  TOP w0.254: JP1.2 77.165,73.96 U1.3
N_5: R5.1 U3.1 | length 5.2
  TOP w0.254: R5.1 69.53,39.05 69.82,38.76 U3.1
N_6: R6.1 U3.5 | length 5.2
  TOP w0.254: R6.1 69.53,36.51 69.78,36.76 U3.5
N_7: R7.1 U3.9 | length 5.4
  TOP w0.254: R7.1 69.53,33.97 70.32,34.76 U3.9
N_8: R8.1 U3.10 | length 6.2
  TOP w0.254: R8.1 69.53,31.43 72.36,34.26 U3.10
N_9: CON4.1 U2.8 | length 1.7
  TOP w0.254: 95.883,86.04 95.905,86.062 U2.8
N_10: CON5.2 U3.27 U3.28 U3.29 U3.30 | length 5.6
  TOP w0.305: U3.27 80.122,37.26 80.623,37.76 ; U3.28 80.623,37.76 ; U3.29 80.797,38.26 80.96,38.098 ; U3.30 80.615,38.76 80.643,38.733 ; 80.643,37.78 80.623,37.76
N_11: CON5.1 U3.21 U3.22 U3.23 U3.24 | length 6.1
  TOP w0.254: U3.23 80.643,35.26 80.231,35.672 80.142,35.76 U3.24
  TOP w0.305: U3.21 80.933,34.26 80.96,34.288 80.487,34.76 U3.22
N_12: pad.@77.785,46.67 pad.@79.055,41.59 U1.7 U3.33 U3.35 | length 53.6
  TOP w0.254: U1.7 74.565,68.305 73.975,68.895 70.8,68.895 65.085,63.18 65.085,56.195 73.975,47.94 76.515,47.94 77.785,46.67 77.785,42.86 76.765,41.84 U3.35 ; U3.33 77.765,40.3 pad.@79.055,41.59
  BOTTOM w0.254: pad.@77.785,46.67 80.325,44.13 80.325,42.86 pad.@79.055,41.59
N_13: pad.@76.515,45.4 pad.@79.055,44.13 U1.6 U3.34 U3.36 | length 54.7
  TOP w0.254: U1.6 75.215,68.925 74.61,69.53 70.165,69.53 64.45,63.815 64.45,55.56 73.34,47.305 75.88,47.305 76.515,46.67 76.515,45.4 76.515,42.543 76.265,42.293 U3.36 ; U3.34 77.265,41.07 79.055,42.86 pad.@79.055,44.13
  BOTTOM w0.254: pad.@76.515,45.4 77.785,45.4 pad.@79.055,44.13
N_14: pad.@66.355,59.37 pad.@70.8,40.955 U1.8 U3.40 | length 36.8
  TOP w0.254: pad.@66.355,59.37 66.355,62.545 70.21,66.4 U1.8 ; pad.@70.8,40.955 73.34,40.955 74.265,40.03 U3.40
  BOTTOM w0.254: pad.@66.355,59.37 70.8,54.925 pad.@70.8,40.955
N_15: R9.1 U3.39 | length 8.5
  TOP w0.254: R9.1 70.165,42.86 71.435,41.59 73.975,41.59 74.765,40.8 U3.39
N_16: CON4.2 U2.11 | length 1.7
  TOP w0.254: 97.788,86.04 97.855,86.108 U2.11
N_17: C13.1 pad.@66.99,28.255 pad.@67.625,55.56 R12.1 U1.9 U3.15 | length 58.3
  TOP w0.254: pad.@66.99,28.255 C13.1 R12.1@69.53,26.715 ; pad.@67.625,55.56 67.625,62.545 70.83,65.75 U1.9 ; R12.1 R12.1@69.53,26.715 ; U3.15 76.265,31.18 74.61,29.525 70.165,29.525 69.53,28.89 R12.1@69.53,26.715
  BOTTOM w0.254: pad.@66.99,28.255 66.99,54.925 pad.@67.625,55.56
N_18: C14.1 pad.@68.895,55.56 pad.@72.07,28.255 R13.1 U1.10 U3.16 | length 53.9
  TOP w0.254: pad.@68.895,55.56 68.895,62.545 71.45,65.1 U1.10 ; pad.@72.07,28.255 C14.1 72.12,26.665 R13.1 74.61,27.62 76.765,29.775 U3.16
  BOTTOM w0.254: pad.@68.895,55.56 68.895,54.925 68.26,54.29 68.26,32.065 pad.@72.07,28.255
N_19: pad.@73.34,32.065 pad.@79.055,58.1 U1.21 U3.11 | length 34.6
  TOP w0.254: pad.@73.34,32.065 74.265,32.99 U3.11 ; U1.21 78.465,59.325 79.055,58.735 pad.@79.055,58.1
  BOTTOM w0.254: pad.@73.34,32.065 72.705,32.7 72.705,51.75 pad.@79.055,58.1
N_20: pad.@73.975,30.795 pad.@77.15,58.1 U1.20 U3.12 | length 37.5
  TOP w0.254: pad.@73.975,30.795 74.765,31.585 U3.12 ; pad.@77.15,58.1 77.15,58.735 77.815,59.4 U1.20
  BOTTOM w0.254: pad.@73.975,30.795 73.34,30.795 72.07,32.065 72.07,53.02 pad.@77.15,58.1
N_21: CON6.1 R10.P_2 | length 6.9
  TOP w1.778: R10.P_2 110.17,49.34 CON6.1
N_22: pad.@71.435,61.275 pad.@87.31,83.5 U1.14 U2.5 | length 46.8
  TOP w0.254: pad.@71.435,61.275 72.66,62.5 U1.14 ; pad.@87.31,83.5 92.39,83.5 93.955,85.065 U2.5
  BOTTOM w0.254: pad.@71.435,61.275 69.53,63.18 69.53,68.26 70.8,69.53 77.15,69.53 87.31,79.69 pad.@87.31,83.5
N_23: pad.@71.435,62.545 pad.@88.58,84.77 U1.13 U2.3 | length 42.7
  TOP w0.254: pad.@71.435,62.545 72.04,63.15 U1.13 ; pad.@88.58,84.77 91.12,84.77 92.655,86.305 U2.3
  BOTTOM w0.254: pad.@71.435,62.545 70.165,63.815 70.165,67.625 71.435,68.895 77.785,68.895 88.58,79.69 pad.@88.58,84.77
N_24: pad.@71.435,63.815 pad.@89.85,86.04 U1.12 U2.1 | length 38.6
  TOP w0.254: pad.@71.435,63.815 72.72,63.8 U1.12 ; pad.@89.85,86.04 90.803,86.04 91.355,86.592 U2.1
  BOTTOM w0.254: pad.@71.435,63.815 71.435,67.625 72.07,68.26 78.42,68.26 89.85,79.69 pad.@89.85,86.04
N_25: pad.@70.8,59.37 pad.@89.85,96.2 U1.15 U2.24 | length 54.6
  TOP w0.254: pad.@70.8,59.37 73.34,59.37 74.565,60.595 U1.15 ; pad.@89.85,96.2 91.12,96.2 91.355,95.965 U2.24
  BOTTOM w0.254: pad.@70.8,59.37 68.895,61.275 68.895,75.245 pad.@89.85,96.2
N_26: pad.@70.8,58.1 pad.@89.85,97.47 U1.16 U2.22 | length 61.2
  TOP w0.254: pad.@70.8,58.1 73.023,58.1 75.215,60.293 U1.16 ; pad.@89.85,97.47 91.755,97.47 92.655,96.57 U2.22
  BOTTOM w0.254: pad.@70.8,58.1 68.26,60.64 68.26,75.88 pad.@89.85,97.47
N_27: pad.@70.8,56.83 pad.@89.85,98.74 U1.17 U2.20 | length 67.8
  TOP w0.254: pad.@70.8,56.83 72.705,56.83 75.865,59.99 U1.17 ; pad.@89.85,98.74 92.39,98.74 93.955,97.175 U2.20
  BOTTOM w0.254: pad.@70.8,56.83 67.625,60.005 67.625,76.515 pad.@89.85,98.74
N_28: CON3.1 U2.14 | length 1.7
  TOP w0.254: 97.788,96.2 97.855,96.133 U2.14
N_29: CON3.2 U2.17 | length 2.1
  TOP w0.254: U2.17 95.905,96.222 96.2,96.518
N_30: D2.A R11.1 | length 2.1
  TOP w0.254: R11.1 D2.A
N_31: Q1.3 R10.P_1
N_32: Q1.1 U1.18 | length 29
  TOP w0.254: U1.18 76.515,59.37 75.88,58.735 75.88,56.83 82.55,50.16 Q1.1
N_33: JP3.1 R4.1 | length 2.9
  TOP w0.254: R4.1 JP3.1
N_34: JP2.1 R3.1 | length 2.9
  TOP w0.254: R3.1 JP2.1
N_35: JP1.1 R2.1 | length 2.9
  TOP w0.254: R2.1 JP1.1
N_36: R14.2 U3.18 | length 7.8
  TOP w0.254: U3.18 77.765,29.545 79.69,27.62 R14.2
N_37: R15.2 U3.17 | length 7
  TOP w0.254: R15.2 77.15,28.255 77.265,28.37 U3.17
N_41: C6.1 CON2.2 L2.1 ZD1.1 | length 30
  TOP w0.254: CON2.2 52.9,93.66 ZD1.1 53.02,93.66 55.925,93.66 C6.1 56.56,93.39 56.83,93.66 L2.1
VBAT: C3.1 C4.2 C5.1 D1.A L1.2 U1.1 | length 29
  TOP w0.254: C5.1@78.42,70.435 C5.1 78.465,69.94 U1.1
  TOP w1.016: L1.2 68.23,79.69 D1.A 72.465,79.72 C3.1@72.432,79.74 ; C5.1@78.42,70.435 C4.2 C3.1@72.432,79.74 ; C3.1@72.432,79.74 72.29,79.74 C3.1 C3.1@72.432,79.74
VCC: C8.2 C11.2 pad.@69.53,45.4 pad.@70.8,37.78 pad.@75.245,45.4 pad.@78.42,23.175 pad.@80.96,63.815 R14.1 R15.1 U1.24 U1.25 U3.2 U3.37 U3.38 | length 75.4
  TOP w0.254: pad.@69.53,45.4 75.245,45.4 75.245,43.765 C11.2 74.975,43.13 75.265,42.84 75.265,40.955 ; pad.@70.8,37.78 71.28,38.26 U3.2 ; U3.38 75.265,40.955 ; U3.37 75.765,40.955 75.265,40.955 ; R15.1 77.15,23.81 77.785,23.175 78.42,23.175 79.055,23.175 79.69,23.81 R14.1 ; U1.24 79.39,63.815 pad.@80.96,63.815 ; U1.25 80.801,64.45 80.96,64.291 pad.@80.96,63.815 ; C8.2 81.85,63.8 80.975,63.8 pad.@80.96,63.815
  BOTTOM w0.254: pad.@69.53,45.4 69.53,37.78 ; pad.@70.8,37.78 69.53,37.78 ; pad.@75.245,45.4 75.245,52.385 80.325,57.465 80.325,63.18 pad.@80.96,63.815 ; pad.@78.42,23.175 78.42,24.445 69.53,32.7 69.53,37.78
VDD: C9.2 U1.22 | length 3.6
  TOP w0.254: U1.22 80.37,62.5 81.595,61.275 C9.2
pads on no net: U1.2 U1.11 U1.19 U1.23 U1.E_PAD U2.2 U2.6 U2.7 U2.10 U2.15 U2.18 U2.19 U2.23 U3.3 U3.4 U3.4T U3.6 U3.8 U3.13 U3.14

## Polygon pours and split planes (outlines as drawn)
GND on TOP "TOP15" (solid, pour order 19): 20.575,20.5 cw(c20.575,20.575) 20.5,20.575 20.5,119.425 cw(c20.575,119.425) 20.575,119.5 119.425,119.5 cw(c119.425,119.425) 119.5,119.425 119.5,20.575 cw(c119.425,20.575) 119.425,20.5
N_10 on TOP "TOP14" (solid, pour order 18): 101.946,37.018 cw(c101.946,37.093) 101.893,37.04 100.645,38.288 81.976,38.288 81.045,37.357 cw(c80.992,37.41) 80.992,37.336 80.273,37.336 cw(c80.273,37.41) 80.198,37.41 80.198,43.524 cw(c80.273,43.524) 80.225,43.581 81.764,44.874 cw(c81.813,44.817) 81.813,44.892 82.23,44.891 82.293,44.89 110.776,44.89 cw(c110.776,44.815) 110.829,44.868 112.18,43.517 cw(c112.127,43.464) 112.202,43.464 112.202,37.43 cw(c112.127,37.43) 112.18,37.377 111.843,37.04 cw(c111.79,37.093) 111.79,37.018
+12V on TOP "TOP13" (solid, pour order 17): 82.198,35.113 cw(c82.198,35.188) 82.145,35.135 81.214,36.066 80.42,36.066 cw(c80.42,36.14) 80.367,36.087 80.22,36.234 cw(c80.273,36.287) 80.198,36.287 80.198,36.733 cw(c80.273,36.733) 80.22,36.786 80.367,36.933 cw(c80.42,36.88) 80.42,36.955 81.214,36.955 82.145,37.885 cw(c82.198,37.832) 82.198,37.907 90.2,37.907 cw(c90.2,37.832) 90.253,37.885 90.59,37.548 cw(c90.537,37.495) 90.612,37.495 90.612,35.525 cw(c90.537,35.525) 90.59,35.472 90.253,35.135 cw(c90.2,35.188) 90.2,35.113
GND on TOP "TOP12" (solid, pour order 16): 76.337,38.415 cw(c76.337,38.49) 76.262,38.49 76.262,38.606 cw(c76.336,38.617) 76.261,38.617 76.261,38.721 cw(c76.336,38.721) 76.336,38.796 76.694,38.796 cw(c76.694,38.721) 76.769,38.721 76.769,38.49 cw(c76.694,38.49) 76.694,38.415
GND on TOP "TOP11" (solid, pour order 15): 74.304,36.256 cw(c74.304,36.331) 74.229,36.331 74.229,36.689 cw(c74.304,36.689) 74.304,36.764 74.535,36.764 cw(c74.535,36.689) 74.61,36.689 74.61,36.331 cw(c74.535,36.331) 74.535,36.256
GND on TOP "TOP10" (solid, pour order 14): 76.336,34.224 cw(c76.336,34.299) 76.261,34.299 76.261,34.594 cw(c76.336,34.594) 76.336,34.669 76.694,34.669 cw(c76.694,34.594) 76.769,34.594 76.769,34.299 cw(c76.694,34.299) 76.694,34.224
GND on TOP "TOP9" (solid, pour order 13): 78.495,36.256 cw(c78.495,36.331) 78.42,36.331 78.42,36.689 cw(c78.495,36.689) 78.495,36.764 78.726,36.764 cw(c78.726,36.689) 78.801,36.689 78.801,36.331 cw(c78.726,36.331) 78.726,36.256
N_11 on TOP "TOP8" (solid, pour order 12): 81.626,28.128 cw(c81.626,28.203) 81.573,28.15 80.22,29.503 cw(c80.273,29.556) 80.198,29.556 80.198,35.61 cw(c80.273,35.61) 80.273,35.685 80.992,35.685 cw(c80.992,35.61) 81.045,35.663 82.018,34.69 cw(c81.965,34.637) 82.04,34.637 82.04,33.081 82.294,32.827 98.677,32.827 101.83,35.98 cw(c101.883,35.927) 101.883,36.002 111.726,36.002 cw(c111.726,35.927) 111.779,35.98 112.18,35.579 cw(c112.127,35.526) 112.202,35.526 112.202,29.556 cw(c112.127,29.556) 112.18,29.503 110.827,28.15 cw(c110.774,28.203) 110.774,28.128
N_31 on TOP "TOP7" (solid, pour order 11): 98.688,46.543 cw(c98.688,46.618) 98.613,46.618 98.613,51.802 cw(c98.688,51.802) 98.688,51.877 105.757,51.877 cw(c105.757,51.802) 105.81,51.855 106.465,51.2 cw(c106.412,51.147) 106.487,51.147 106.487,47.273 cw(c106.412,47.273) 106.465,47.22 105.81,46.565 cw(c105.757,46.618) 105.757,46.543
N_9 on TOP "TOP6" (solid, pour order 10): 95.279,78.611 cw(c95.279,78.685) 95.226,78.632 94.507,79.351 cw(c94.56,79.404) 94.486,79.404 94.486,86.41 cw(c94.56,86.41) 94.56,86.485 96.57,86.485 cw(c96.57,86.41) 96.645,86.41 96.645,80.96 97.143,80.462 97.47,80.462 111.408,80.769 cw(c111.41,80.694) 111.463,80.747 111.863,80.347 cw(c111.81,80.294) 111.885,80.294 111.885,79.086 cw(c111.81,79.086) 111.863,79.033 111.462,78.632 cw(c111.409,78.685) 111.409,78.611
N_16 on TOP "TOP5" (solid, pour order 9): 98.136,81.151 cw(c98.136,81.225) 98.083,81.172 97.365,81.891 cw(c97.418,81.944) 97.343,81.944 97.343,86.41 cw(c97.418,86.41) 97.418,86.485 99.427,86.485 cw(c99.427,86.41) 99.502,86.41 99.502,83.818 100.01,83.31 111.409,83.31 cw(c111.409,83.235) 111.462,83.288 111.863,82.887 cw(c111.81,82.834) 111.885,82.834 111.885,81.626 cw(c111.81,81.626) 111.863,81.573 111.462,81.172 cw(c111.409,81.225) 111.409,81.151
+12V on TOP "TOP4" (solid, pour order 8): 99.005,87.183 cw(c99.005,87.258) 98.931,87.258 98.931,94.982 cw(c99.005,94.982) 99.005,95.057 106.646,95.057 cw(c106.646,94.982) 106.699,95.035 107.418,94.317 cw(c107.365,94.264) 107.44,94.264 107.44,87.976 cw(c107.365,87.976) 107.418,87.923 106.699,87.205 cw(c106.646,87.258) 106.646,87.183
N_28 on TOP "TOP3" (solid, pour order 7): 97.418,95.756 cw(c97.418,95.83) 97.343,95.83 97.343,100.296 cw(c97.418,100.296) 97.365,100.349 98.083,101.068 cw(c98.136,101.015) 98.136,101.09 111.409,101.09 cw(c111.409,101.015) 111.462,101.068 111.863,100.667 cw(c111.81,100.614) 111.885,100.614 111.885,99.406 cw(c111.81,99.406) 111.863,99.353 111.462,98.952 cw(c111.409,99.005) 111.409,98.931 100.01,98.931 99.502,98.423 99.502,95.83 cw(c99.427,95.83) 99.427,95.756
N_29 on TOP "TOP2" (solid, pour order 6): 94.56,95.756 cw(c94.56,95.83) 94.486,95.83 94.486,102.836 cw(c94.56,102.836) 94.507,102.889 95.226,103.608 cw(c95.279,103.555) 95.279,103.63 111.409,103.63 cw(c111.409,103.555) 111.462,103.608 111.863,103.207 cw(c111.81,103.154) 111.885,103.154 111.885,101.946 cw(c111.81,101.946) 111.863,101.893 111.462,101.492 cw(c111.409,101.545) 111.409,101.471 97.153,101.471 96.645,100.963 96.645,95.83 cw(c96.57,95.83) 96.57,95.756
GND on TOP "TOP1" (solid, pour order 5): 93.111,95.499 cw(c93.111,95.574) 93.036,95.574 93.036,96.57 ccw(c92.655,96.57) 92.924,96.84 92.024,97.74 ccw(c91.755,97.47) 91.755,97.851 90.284,97.851 cw(c90.284,97.926) 90.231,97.873 90.102,98.002 cw(c90.155,98.055) 90.08,98.055 90.08,98.155 cw(c90.155,98.155) 90.102,98.208 90.231,98.337 cw(c90.284,98.284) 90.284,98.359 92.201,98.359 cw(c92.201,98.284) 92.254,98.337 93.552,97.039 cw(c93.499,96.986) 93.574,96.986 93.574,95.574 cw(c93.499,95.574) 93.499,95.499
GND on BOTTOM "BOTTOM18" (solid, pour order 4): 80.477,44.548 cw(c80.477,44.623) 80.424,44.57 78.361,46.633 cw(c78.414,46.686) 78.339,46.686 78.339,46.9 78.015,47.224 77.555,47.224 77.231,46.9 77.231,46.44 77.555,46.116 77.769,46.116 cw(c77.769,46.041) 77.822,46.094 77.995,45.92 cw(c77.942,45.867) 78.017,45.867 78.017,45.828 cw(c77.942,45.828) 77.917,45.758 ccw(c77.785,45.4) 77.785,45.781 76.949,45.781 cw(c76.949,45.856) 76.896,45.803 76.745,45.954 76.285,45.954 75.961,45.63 cw(c75.901,45.675) 75.9,45.6 75.859,45.6 cw(c75.859,45.675) 75.799,45.63 75.648,45.781 cw(c75.701,45.834) 75.626,45.834 75.626,52.196 cw(c75.701,52.196) 75.648,52.249 80.446,57.047 cw(c80.499,56.994) 80.499,57.068 80.504,57.068 cw(c80.504,56.994) 80.579,56.994 80.579,44.623 cw(c80.504,44.623) 80.504,44.548
GND on BOTTOM "BOTTOM17" (solid, pour order 3): 20.575,20.5 cw(c20.575,20.575) 20.5,20.575 20.5,119.425 cw(c20.575,119.425) 20.575,119.5 119.425,119.5 cw(c119.425,119.425) 119.5,119.425 119.5,20.575 cw(c119.425,20.575) 119.425,20.5
+12V on BOTTOM "BOTTOM16" (solid, pour order 2): 81.563,35.113 cw(c81.563,35.188) 81.51,35.135 80.855,35.79 cw(c80.908,35.843) 80.833,35.843 80.833,58.132 cw(c80.908,58.132) 80.855,58.185 82.145,59.475 cw(c82.198,59.422) 82.198,59.497 97.407,59.497 98.613,60.704 98.613,97.407 97.407,98.613 90.479,98.613 cw(c90.479,98.688) 90.404,98.688 90.404,98.97 90.08,99.294 89.62,99.294 89.296,98.97 89.296,98.725 cw(c89.221,98.725) 89.274,98.672 89.237,98.635 cw(c89.184,98.688) 89.184,98.613 56.83,98.613 55.687,97.47 55.687,74.578 cw(c55.612,74.578) 55.665,74.525 54.375,73.235 cw(c54.322,73.288) 54.322,73.213 28.858,73.213 cw(c28.858,73.288) 28.805,73.235 27.515,74.525 cw(c27.568,74.578) 27.493,74.578 27.493,79.722 cw(c27.568,79.722) 27.515,79.775 28.805,81.065 cw(c28.858,81.012) 28.858,81.087 46.607,81.087 47.813,82.294 47.813,105.122 cw(c47.888,105.122) 47.835,105.175 49.125,106.465 cw(c49.178,106.412) 49.178,106.487 105.122,106.487 cw(c105.122,106.412) 105.175,106.465 106.465,105.175 cw(c106.412,105.122) 106.487,105.122 106.487,52.988 cw(c106.412,52.988) 106.465,52.935 105.175,51.645 cw(c105.122,51.698) 105.122,51.623 89.85,51.623 88.707,50.48 88.707,35.843 cw(c88.632,35.843) 88.685,35.79 88.03,35.135 cw(c87.977,35.188) 87.977,35.113

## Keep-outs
Keep-Out Layer:
  lines w0.1: 20,20 120,20 120,120 20,120 20,20 ; 23,21.4 cw(c23,23) 23,24.6 cw(c23,23) 23,21.4 ; 23,115.4 cw(c23,117) 23,118.6 cw(c23,117) 23,115.4 ; 117,21.4 cw(c117,23) 117,24.6 cw(c117,23) 117,21.4 ; 117,115.4 cw(c117,117) 117,118.6 cw(c117,117) 117,115.4

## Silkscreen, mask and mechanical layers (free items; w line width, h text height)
Top Overlay:
  text "M1" at 109.3,105.3 h0.89
  text "+" at 106.622,102.55 h0.99
  text "-" at 106.622,100.01 h0.99
  text "GND" at 32.8,95.2 h1.07
  text "BUS" at 32.9,92.7 h1.07
  text "-" at 106.622,82.23 h0.99
  text "GND" at 32.7,81.7 h0.79
  text "TB9101FTG" at 88.18,80.3 h1.6
  text "+" at 106.622,79.69 h0.99
  text "VBAT" at 32.8,78.9 h0.79
  text "M2" at 109.1,76.1 h0.89
  text "POWER" at 37.3,71 h0.99
  text "TB9033FTG" at 54.48,63.8 h1.6
  text "LED" at 108.8,60.8 h0.89
  text "+" at 106.622,58.1 h0.99
  text "-" at 106.622,55.56 h0.99
  text "SSM3K341R" at 93.66,52.4 h1.07
  text "TB9054FTG" at 68.88,48.4 h1.6
  text "M3" at 109.5,40.6 h0.89
  text "-" at 106.622,37.78 h0.99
